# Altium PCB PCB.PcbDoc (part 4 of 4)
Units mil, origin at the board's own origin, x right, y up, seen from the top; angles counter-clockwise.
Board outline 6311.26 x 4737.49 mil, 2 copper layers (Top Layer, Bottom Layer); 252 components, 238 nets, 1140 pads, 635 vias.
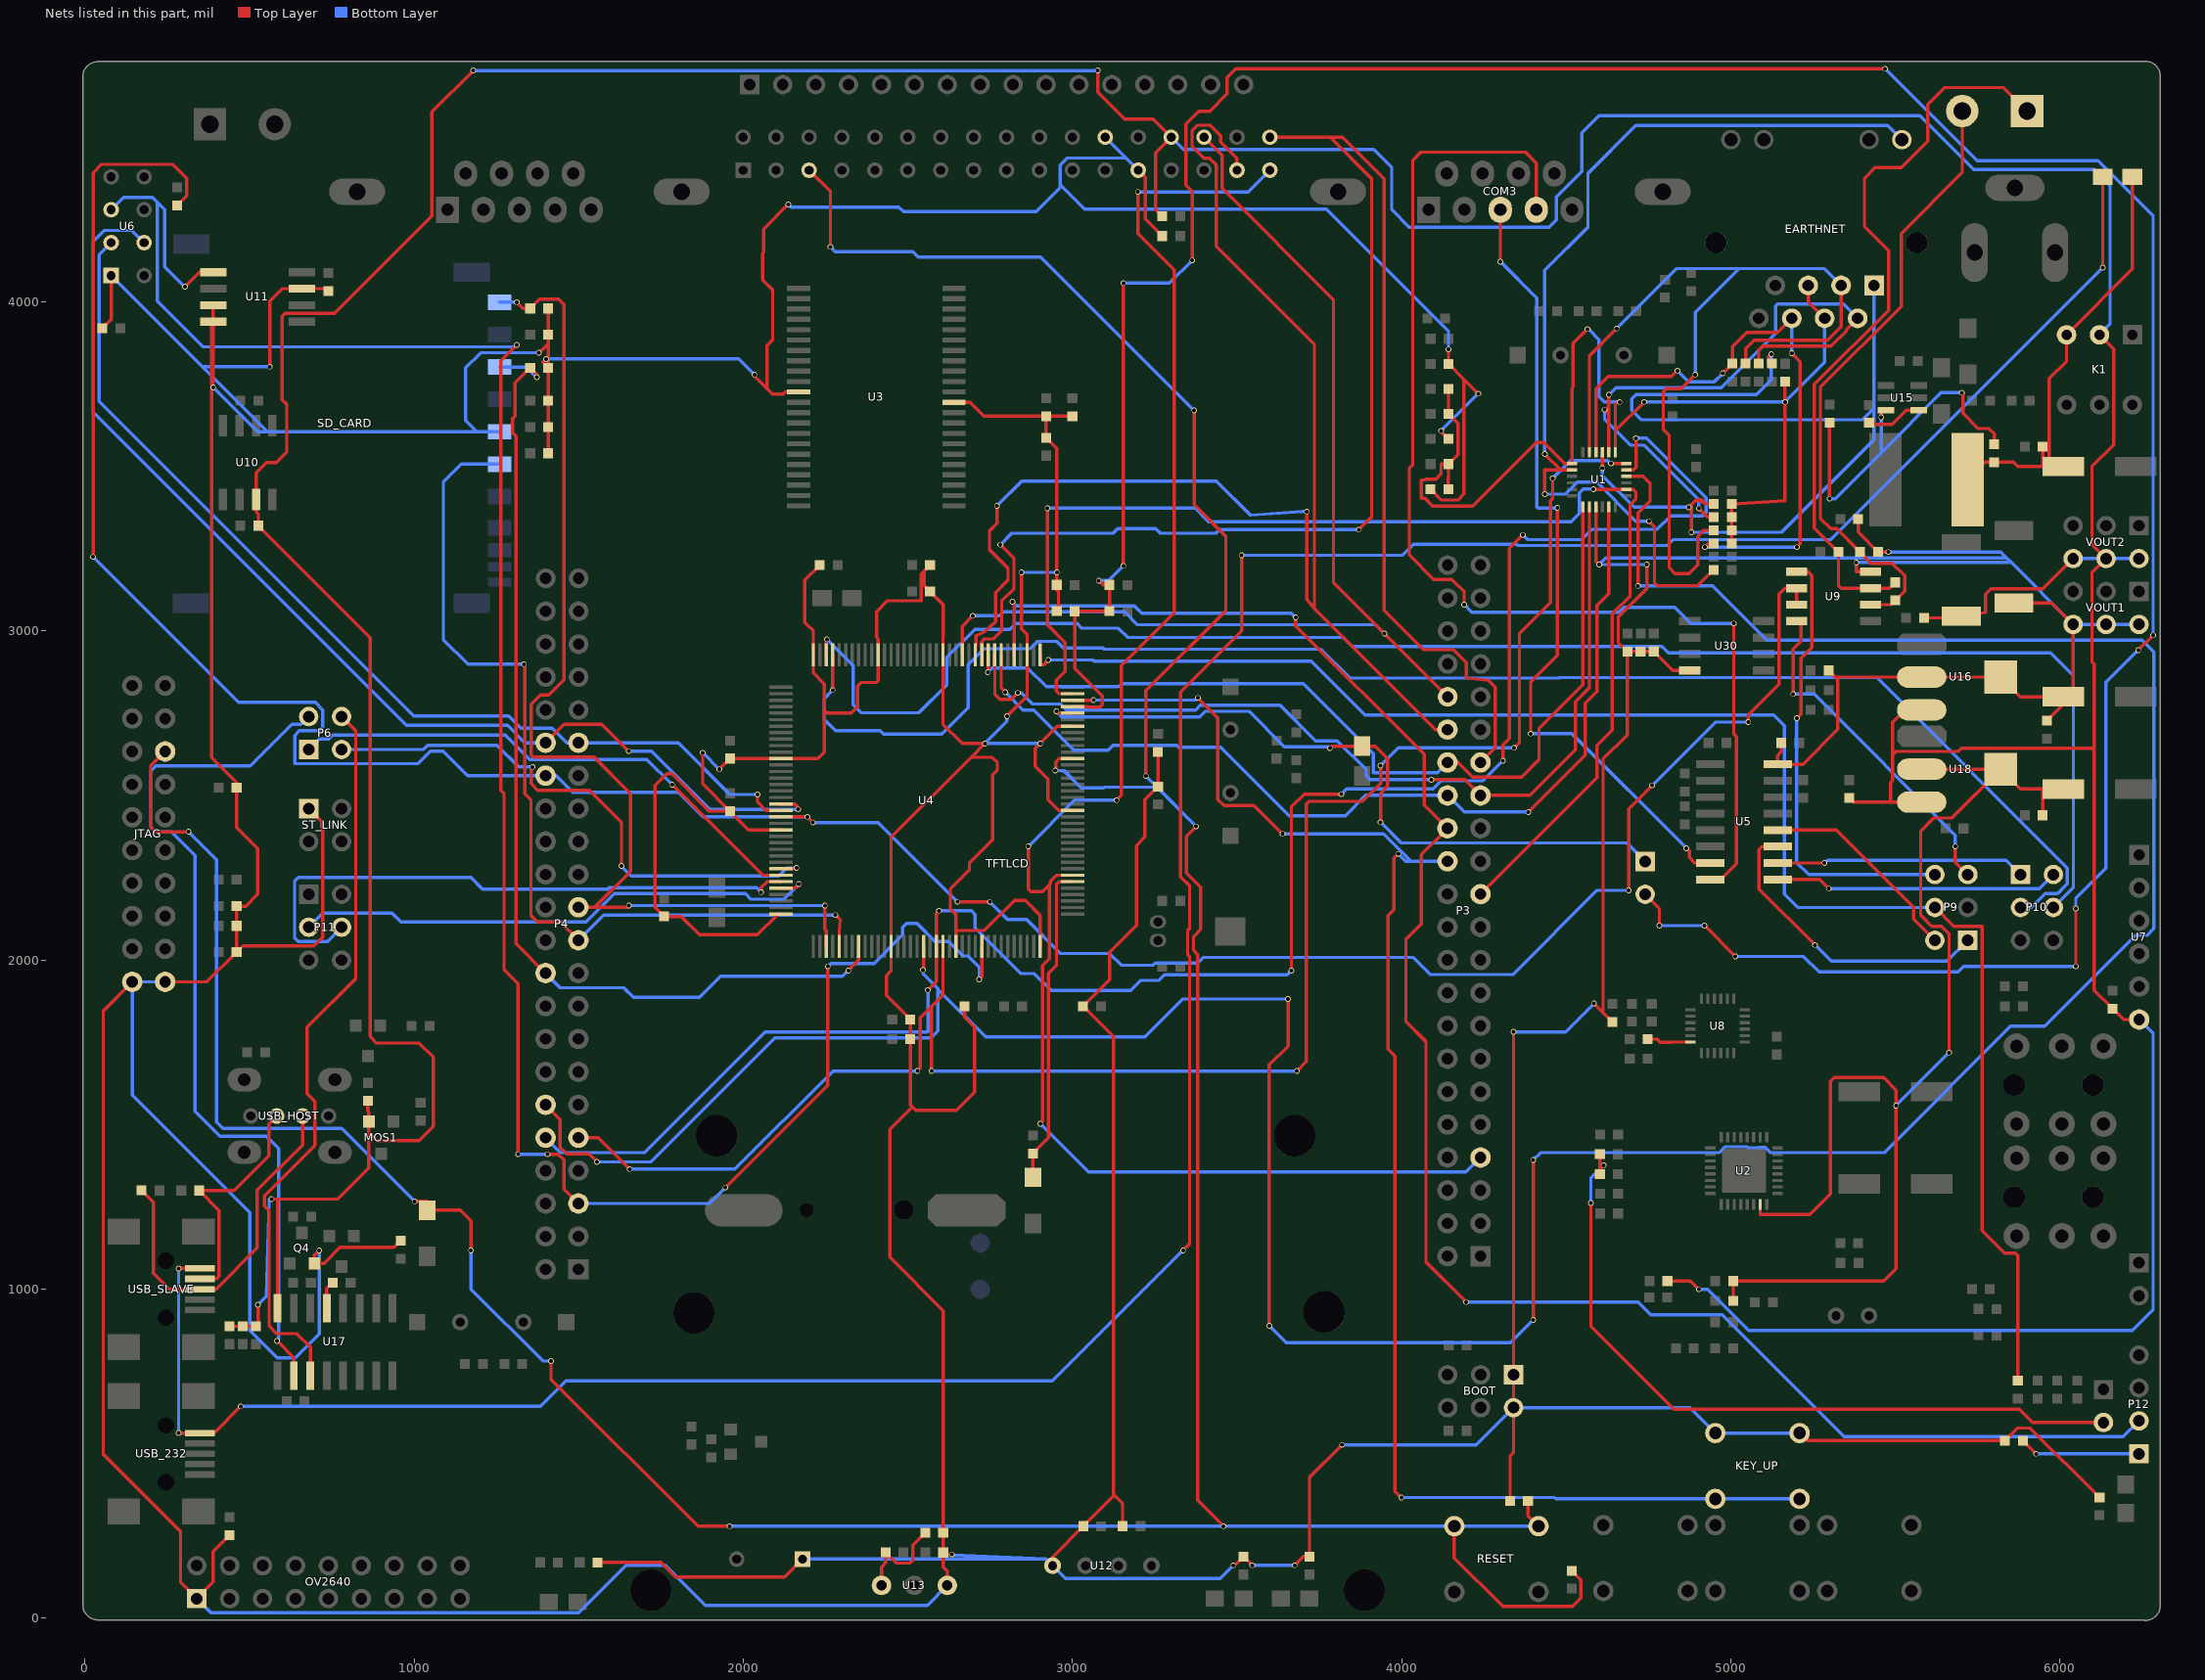
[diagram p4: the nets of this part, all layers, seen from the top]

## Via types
v1: diameter 17, hole 12, Top Layer to Bottom Layer, 622 vias
v2: diameter 25, hole 15, Top Layer to Bottom Layer, 9 vias
v3: diameter 275.59, hole 129.92, Top Layer to Bottom Layer, 4 vias

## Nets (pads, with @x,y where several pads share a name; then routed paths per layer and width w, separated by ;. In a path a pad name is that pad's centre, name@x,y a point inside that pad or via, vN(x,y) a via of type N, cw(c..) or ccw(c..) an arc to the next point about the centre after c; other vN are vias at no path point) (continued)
NetR38_2: 485.2 R38.2 R44.1 U9.6 | length 1911.7
  Top Layer w10: U9.6@5424.41,3080 5487,3080 R44.1@5500,3093 5528.06,3121.06 5528.06,3168 5490.06,3206 5426.56,3206 R38.2@5392.5,3240.06 5321.56,3311 5304,3311 5272,3343 5272,3740.01 5518,3986.01 5518,4208 5703.15,4393.15 485.2@5703.15,4580
NetR40_1: 485.1 R40.1 R44.2 U9.7 | length 2277.6
  Top Layer w10: R44.2@5500.06,3147.5 5482.56,3130 U9.7@5424.41,3130 5336,3130 5327,3139 R40.1@5327,3240 5254,3313 5254,3749.31 5479,3974.31 5479,4155 5406,4228 5406,4376 5438,4408 5518,4408 5598,4488 5598,4600 5649,4651 5829,4651 485.1@5900,4580
NetR45_2: R45.2 U8.12 | length 133.8
  Top Layer w9.84: 4819,1750.79 U8.12@4877.28,1750.79
  Top Layer w10: R45.2@4747.5,1759.94 4775.69,1759.94 4785.13,1750.5 4818.71,1750.5 4819,1750.79
NetR63_2: R63.2 R66.1 U13.1 | length 304.1
  Top Layer w10: U13.1@2420,100 2420,155.5 2432.5,168 R63.2@2432.5,200.06 2464.56,168 2507,168 2515,176 2515,222 R66.1@2553,260
NetR67_1: R67.1 R69.2 U15.3 | length 1356.4
  Top Layer w10: v1(5457,3649) 5457,3671.2 U15.3@5471,3671.2 ; v1(5702,3724) 5705,3721 5705,3662 5752,3615 5784,3615 5800.06,3598.94 R69.2@5800.06,3567.5 ; v1(5300,3402) R67.1@5300,3633 v1(5300,3402)
  Bottom Layer w10: v1(5300,3402) 5317,3402 5457,3542 ; v1(5457,3649) 5457,3542 ; v1(5702,3724) 5639,3724 5457,3542
NetR68_2: R68.2 U15.4 | length 171.2
  Top Layer w10: R68.2@5419.94,3632.5 5435.2,3632.5 5440.2,3627.5 5489.3,3627.5 5533,3671.2 U15.4@5571,3671.2
NetR71_1: R71.1 U17.13 | length 85.1
  Top Layer w10: U17.13@735,942.36 735,1002 R71.1@753,1020
NRF_CE: P4.34 U4.91 U6.3 | length 3454.7
  Top Layer w10: P4.34@1399.58,2660.43 1456.15,2717 1570,2717 v1(1652,2635) ; U4.91@2114.53,2474.62 2156.38,2474.62 2167,2464 v1(2167,2458)
  Bottom Layer w10: U6.3@180,4180 143,4217 58,4217 25,4184 25,3665 977,2713 1284,2713 1336.57,2660.43 P4.34@1399.58,2660.43 ; v1(1652,2635) 1721.5,2635 1898.5,2458 v1(2167,2458)
NRF_CS: P4.33 U4.92 U6.4 | length 3097.2
  Top Layer w10: v1(2043.52,2503) 2043.52,2480 2068.58,2454.94 U4.92@2114.53,2454.94
  Bottom Layer w10: U6.4@80,4180 43,4143 43,3698 999,2742 1287.43,2742 1325,2704.43 1420,2704.43 1464,2660.43 P4.33@1499.58,2660.43 1802.74,2660.43 1960.17,2503 v1(2043.52,2503)
NRF_IRQ: P4.32 R37.1 U4.93 U9.2 U9.3 | length 8512.1
  Top Layer w10: v1(25,3225) 25,4392 51,4418 267,4418 309,4376 309,4322 R37.1@280,4293 ; U4.93@2114.53,2435.25 v1(2194.75,2435.25) v1(2212,2418) ; v1(2651,2177) v1(2749,2177) ; v1(4690,2212) 4690,2460 v1(4761,2531) ; v1(5053,2723) 5053,2745 5146,2838 5146,3112 5164,3130 U9.2@5200,3130 U9.3@5200,3080
  Bottom Layer w10: v1(25,3225) 467,2783 700,2783 723,2760 723,2708 712,2697 651.94,2697 637.47,2682.53 637.47,2597 1012,2597 1049.5,2634.5 1088,2634.5 1162.07,2560.43 P4.32@1399.58,2560.43 1431.57,2560.43 1482,2510 1802.76,2510 1877.51,2435.25 v1(2194.75,2435.25) ; v1(2212,2418) 2410,2418 v1(2651,2177) ; v1(2749,2177) 2803,2123 2861,2123 2964,2020 3113,2020 3148.5,1984.5 3245.47,1984.5 3251.97,1991 3380,1991 3397,2008 4036,2008 4088,1956 4338.02,1956 4594.02,2212 v1(4690,2212) ; v1(4761,2531) 4953,2723 v1(5053,2723)
PA0: KEY_UP.2 P3.26 U4.34 | length 4849.1
  Top Layer w10: U4.34@3000.35,2789.58 3063.58,2789.58 v1(3064,2790) ; v1(3381,2797) 3442,2736 3442,2488 3460.13,2469.87 3552,2469.87 v1(3638.33,2383.55) ; v1(3990,2323) 3977.09,2310.09 3977.09,2153.81 3959.09,2135.81 3959.09,1729.53 3980,1708.63 3980,386 v1(3999,367)
  Bottom Layer w10: v1(3064,2790) 3374,2790 v1(3381,2797) ; v1(3638.33,2383.55) 3945.45,2383.55 3998,2331 4028.57,2300.43 ; v1(3990,2323) 4012.57,2300.43 4028.57,2300.43 ; v1(3999,367) 4464,367 4468,363 KEY_UP.2@4953,363 KEY_UP.2@5208.91,363 ; 4028.57,2300.43 P3.26@4139.58,2300.43 4028.57,2300.43
PA1: P3.23 U1.14 U4.35 | length 3944.6
  Top Layer w9.84: v1(4583,3430.47) U1.14@4682.72,3430.47 4704,3430.47 4711.58,3422.89 4711.58,3399.58 4694,3382
  Top Layer w10: v1(2924,3373) 2924,3019 2977.94,2965.06 2977.94,2876.88 2951,2849.94 2951,2818.27 2960,2809.27 U4.35@3000.35,2809.27 ; P3.23@4239.58,2200.43 4594,2554.85 4594,2652 4640,2698 4640,3052 4694,3106 4694,3382
  Bottom Layer w10: v1(2924,3373) 3373,3373 3413.72,3332.28 4514.55,3332.28 4540.08,3357.81 4540.08,3419.58 4552,3431.5 4581.97,3431.5 v1(4583,3430.47)
PA3: P9.4 R20.1 U4.37 | length 4978
  Top Layer w10: U4.37@2901.93,2927.38 2901.93,2897 2912,2897 v1(2927,2912) ; P9.4@5620,2160 5677,2103 5763,2103 5763,1178.52 5832,1109.52 5864.74,1109.52 5872,1102.26 R20.1@5872,722
  Bottom Layer w10: v1(2927,2912) 3062.25,2912 3065.75,2908.5 3725.05,2908.5 3888.55,2745 5130,2745 5163,2712 5163,2200 5203,2160 P9.4@5620,2160
PA5: P3.28 P12.2 U4.41 | length 5676.3
  Top Layer w10: v1(2818,3089) 2823.19,3083.81 U4.41@2823.19,2927.38 ; v1(3678,3041) 3678,3015.39 4068.26,2625.14 4068.26,2471.75 P3.28@4139.58,2400.43 4059.58,2320.43 4059.58,2110.29 4013.09,2063.81 4013.09,1813.41 4074,1752.5 4074,1083 v1(4196,961)
  Bottom Layer w10: v1(2818,3089) 2830.5,3076.5 3188.05,3076.5 3210.41,3054.14 3664.86,3054.14 v1(3678,3041) ; v1(4196,961) 4718.5,961 4757.5,922 4974,922 5344,552 6192,552 P12.2@6240,600
PA7: P3.30 U1.11 U4.43 | length 2949.7
  Top Layer w9.84: 4629.53,3113.24 U1.11@4629.53,3377.28
  Top Layer w10: U4.43@2783.82,2927.38 2783.82,2826.18 v1(2796,2814) ; v1(4385,2450) 4558,2623 4558,2780.5 4593.79,2816.29 4593.79,3077.5 4629.53,3113.24
  Bottom Layer w10: v1(2796,2814) 2850,2760 2883,2760 3005,2638 3108.5,2638 3123,2652.5 3317.5,2652.5 3323,2647 3451,2647 3659,2439 3829.57,2439 3891,2500.43 P3.30@4139.58,2500.43 4190,2450 v1(4385,2450)
PA9: P6.3 U4.101 | length 1724
  Top Layer w10: v1(1360,2587) 1355.58,2582.58 1355.58,2536 1375.58,2516 1533.51,2516 1630,2419.51 v1(1630,2286) ; U4.101@2114.53,2277.77 2159.77,2277.77 v1(2162,2280)
  Bottom Layer w10: P6.3@780,2640 1029,2640 1041.5,2652.5 1252.5,2652.5 1318,2587 v1(1360,2587) ; v1(1630,2286) 1659.86,2256.14 2108.48,2256.14 2132.34,2280 v1(2162,2280)
PA10: P6.1 U4.102 | length 1629.2
  Top Layer w10: v1(1784,2533) 2058.91,2258.09 U4.102@2114.53,2258.09
  Bottom Layer w10: P6.1@680,2640 712.18,2672.18 740.53,2672.18 752.35,2684 1277,2684 1351,2610 1707,2610 v1(1784,2533)
PA11: P11.4 U4.103 | length 1863
  Top Layer w10: v1(2054.4,2206.4) 2054.4,2220.8 2072,2238.4 U4.103@2114.53,2238.4
  Bottom Layer w10: P11.4@780,2100 737,2057 648,2057 637,2068 637,2240 648,2251 1173,2251 1208,2216 1588,2216 1592.14,2220.14 2040.66,2220.14 v1(2054.4,2206.4)
PA12: P11.3 U4.104 | length 1639.4
  Top Layer w10: U4.104@2114.53,2218.72 2156.72,2218.72 v1(2169,2231)
  Bottom Layer w10: P11.3@680,2100 723,2143 933,2143 960,2116 1523,2116 1609,2202 2006.9,2202 2024,2184.9 2122.9,2184.9 v1(2169,2231)
PB0: P3.31 TFTLCD.34 U4.46 | length 5389.3
  Top Layer w10: U4.46@2724.76,2927.38 2724.76,2968 2732.76,2976 2761,2976 2785,3000 2785,3090.5 2822.5,3128 2822.5,3220.5 v1(2781,3262) ; v1(3870,3308) 3909,3347 3909,4374 3782.76,4500.24 ; P3.31@4239.58,2600.43 4284,2644.85 4284,2830 4264,2850 4197,2857 4197,2904 4158,2943 4067,2943 3947,3063 3947,4374 3820.76,4500.24 3782.76,4500.24 ; 3782.76,4500.24 TFTLCD.34@3599.92,4500.24 3782.76,4500.24
  Bottom Layer w10: v1(2781,3262) 2816,3297 3123,3297 3137.5,3311.5 3252.5,3311.5 3267,3297 3436,3297 3447,3308 v1(3870,3308)
PB1: P3.34 TFTLCD.31 U4.47 | length 4255.8
  Top Layer w10: U4.47@2705.08,2927.38 2706.76,2963.68 2706.76,2985.35 2733.58,2998.58 2767,3028 2767,3117 2804.5,3154.5 2804.5,3190 2748,3246.5 2748,3304 2771,3327 v1(2771,3380.5) ; TFTLCD.31@3499.92,4400.24 3499.92,4436.08 3450,4486 3450,4505 3418.14,4536.86 3380.16,4536.86 3363.3,4520 3363.3,4473.54 3399.98,4436.86 3416,4436.86 3436.54,4416.31 3436.54,4169.48 3735,3871.02 3735,3068.57 ; v1(3712,3363) 3712,3096 3735,3068.57 ; P3.34@4139.58,2700.43 4103.15,2700.43 3735,3068.57
  Bottom Layer w10: v1(2771,3380.5) 2846.12,3455.62 3437.38,3455.62 3541,3352 3699,3363 v1(3712,3363)
PB5: P4.5 U4.135 U6.6 U11.5 | length 6818.7
  Top Layer w10: v1(304,4046) 348,4090 U11.5@390,4090 ; v1(1312,3869) 1263.5,3820.5 1263.5,2515.5 1273.5,2505.5 1273.5,1970.5 1316,1928 v1(1316,1410) ; v1(1406,1410) 1438,1410 1455,1393 1455,1305 P4.5@1499.58,1260.43 ; v1(1946,1309) 2257,1620 v1(2257,1981) ; v1(2717,1941) 2724.76,1948.76 U4.135@2724.76,2041.55
  Bottom Layer w10: U6.6@80,4280 117,4317 206,4317 ; v1(304,4046) 243,4107 243,4280 220,4303 ; v1(1312,3869) 1306.38,3863.38 358.71,3863.38 220,4002.08 220,4303 ; v1(1316,1410) v1(1406,1410) ; P4.5@1499.58,1260.43 1897.43,1260.43 v1(1946,1309) ; v1(2257,1981) 2266,1990 2397.46,1990 2484.5,2077.04 2484.5,2100 2496,2111.5 2528,2111.5 2582.5,2057 2624,2057 2668.43,2012.57 2682.81,2012.57 2717,1978.38 v1(2717,1941) ; 206,4317 220,4303 ; 206,4317 220,4303
PB10: P10.3 U4.69 | length 4702.7
  Top Layer w10: v1(2272.01,2820.34) U4.69@2272.01,2927.38
  Bottom Layer w10: v1(2272.01,2820.34) 2245.56,2793.89 2245.56,2731.94 2280,2697.5 2415.5,2697.5 2426.5,2686.5 2603.5,2686.5 2683.5,2766.5 2683.5,2897.76 2731.97,2946.23 2872,2946.23 2894.27,2968.5 2952,2968.5 2972.5,2948 3093.5,2948 3097,2944.5 3754.88,2944.5 3842.38,2857 4478.02,2857 4479.53,2858.51 5444.02,2858.51 6022.53,2280 6022.53,2232 5993.06,2202.53 5955.53,2202.53 5913,2160 P10.3@5880,2160
PB11: P10.4 U4.70 | length 4953.6
  Top Layer w10: U4.70@2252.32,2927.38 2252.32,2973.32 v1(2254,2975)
  Bottom Layer w10: v1(2254,2975) 2334,2895 2334,2776 2358.5,2751.5 2534,2751.5 2618.5,2836 2618.5,2920 2703.49,3004.99 2809.99,3004.99 2827.5,3022.5 3014.5,3022.5 3028.5,3008.5 3139.5,3008.5 3167.5,2980.5 3821.67,2980.5 3849.68,2952.5 4790.64,2952.5 4810.09,2933.05 5971.95,2933.05 6040.53,2864.47 6040.53,2220.53 P10.4@5980,2160
PC4: P3.29 U1.8 U4.44 | length 2863.4
  Top Layer w9.84: 4570.47,2827.47 U1.8@4570.47,3377.28
  Top Layer w10: U4.44@2764.13,2927.38 2764.13,2893.47 2764.5,2893.47 2764.5,2807.63 2780.13,2792 2814,2792 v1(2834,2812) ; v1(4090.5,2548) 4192,2548 P3.29@4239.58,2500.43 4389.43,2500.43 4528,2639 4528,2785 4570.47,2827.47
  Bottom Layer w10: v1(2834,2812) 2845,2812 2879,2778 2963.95,2778 2981.95,2760 3374,2760 3388,2774 3631,2774 3738.5,2666.5 3804.45,2666.5 3892.75,2578.2 3892.75,2559.25 3904,2548 v1(4090.5,2548)
PC5: P3.32 U1.7 U4.45 | length 2782.5
  Top Layer w9.84: 4550.79,2836.28 U1.7@4550.79,3377.28
  Top Layer w10: v1(2743,2875) 2744.45,2876.45 U4.45@2744.45,2927.38 ; P3.32@4139.58,2600.43 4172,2600.43 4216,2556.43 4364.93,2556.43 4417.27,2608.77 4417.27,2702.75 4550.79,2836.28
  Bottom Layer w10: v1(2743,2875) 2755.98,2887.98 2863.12,2887.98 2920.61,2830.49 3140.49,2830.49 3150,2840 3701.32,2840 3914.5,2626.82 3914.5,2569.5 4108.65,2569.5 P3.32@4139.58,2600.43
PC10: P4.23 R42.1 SD_CARD.9 U4.111 | length 3312.7
  Top Layer w10: v1(1312,3999.09) 1331.09,3980 R42.1@1353,3980 1381,4008 1439,4008 1455,3992 1455,2852 1409,2806 1384,2806 1355.58,2777.58 1355.58,2623.31 1362.46,2616.43 1546.94,2616.43 1657.46,2505.91 1657.46,2269.46 1548.43,2160.43 ; v1(1652.8,2165.8) 1647.43,2160.43 1548.43,2160.43 ; v1(2248,2165.8) 2248,2094.32 2252.32,2090 U4.111@2252.32,2041.55 ; 1548.43,2160.43 P4.23@1499.58,2160.43 1548.43,2160.43
  Bottom Layer w10: SD_CARD.9@1259.64,3999.09 v1(1312,3999.09) ; v1(1652.8,2165.8) v1(2248,2165.8)
PC12: P4.21 SD_CARD.5 U4.113 | length 2808.9
  Top Layer w10: v1(1334,2899) 1337,2896 1337,2505 1355,2487 1355,2136 1375,2116 1444,2116 P4.21@1499.58,2060.43 ; v1(2280,2137) 2294.85,2122.15 2291.69,2087.32 U4.113@2291.69,2041.55
  Bottom Layer w10: SD_CARD.5@1259.64,3506.97 1144,3506.97 1089,3451.97 1089,2974 1164,2899 v1(1334,2899) ; P4.21@1499.58,2060.43 1576.15,2137 v1(2280,2137)
PC13: P3.7 TFTLCD.33 U4.7 | length 5171.4
  Top Layer w10: v1(2866,2345.54) 2866,2216 2874,2208 2909,2208 2930.37,2229.37 ; v1(2902,1503) 2909.5,1510.5 2909.5,1984.05 2930.37,2004.93 2930.37,2229.37 ; U4.7@3000.35,2258.09 2952,2258.09 2933,2239.09 2933,2232 ; v1(3134,2486) 3149,2501 3149,2895.05 3309,3055.05 3309,4098 3199,4208 v1(3199,4334) ; 2930.37,2229.37 2933,2232 ; 2930.37,2229.37 2933,2232
  Bottom Layer w10: v1(2866,2345.54) 3006.46,2486 v1(3134,2486) ; v1(2902,1503) 3049,1356 4195.15,1356 P3.7@4239.58,1400.43 ; v1(3199,4334) 3533.69,4334 TFTLCD.33@3599.92,4400.24
PD2: P4.20 R39.1 SD_CARD.2 U4.116 | length 3136.6
  Top Layer w10: v1(1373,3771) 1373,3780 R39.1@1353,3800 1307,3754 1307,3653 1299.5,3645.5 1299.5,3602.31 1309.5,3592.31 1309.5,2050.5 P4.20@1399.58,1960.43 ; v1(2319.24,1968.31) 2350.75,1999.82 U4.116@2350.75,2041.55
  Bottom Layer w10: SD_CARD.2@1260,3802 1342,3802 v1(1373,3771) ; P4.20@1399.58,1960.43 1444,1916 1637,1916 1666.25,1886.75 1867.74,1886.75 1931.49,1950.5 2301.43,1950.5 v1(2319.24,1968.31)
PF11: P3.36 TFTLCD.30 U4.49 | length 3693.5
  Top Layer w10: U4.49@2665.71,2927.38 2665.71,3014.51 v1(2697.38,3046.18) ; TFTLCD.30@3399.92,4500.24 3454.54,4445.61 3454.54,4345.61 3793,4007.16 3793,3147 v1(3948,2992) ; v1(3948,2992) P3.36@4140,2800 v1(3948,2992)
  Bottom Layer w10: v1(2697.38,3046.18) 2779.18,3046.18 2791.5,3058.5 3158.48,3058.5 3198.12,3018.86 3921.14,3018.86 v1(3948,2992)
PG11: P4.12 U1.16 U4.126 | length 10346.9
  Top Layer w9.84: U1.16@4682.72,3469.84 4733.16,3469.84
  Top Layer w10: P4.12@1399.58,1560.43 1444,1516 1444,1431 1464,1411 1532,1411 v1(1556,1387) ; v1@2547.6,1971.6 U4.126@2547.6,2041.55 ; v1(3598,889) 3598,1682 3655,1739 v1(3655,1882) ; v1(4400,907) v1(4400,1393) ; v1(4718,3137) 4718,3359 4755,3396 4755,3448 4733.16,3469.84
  Bottom Layer w10: v1(1556,1387) 1720,1387 2096.5,1763.5 2570.28,1763.5 2590.78,1784 2590.78,1909.22 ; 2546,1959 2590.78,1914.22 ; 2591.5,1911.5 2736.5,1766.5 3220,1766.5 3335.5,1882 v1(3655,1882) ; v1(3598,889) 3649.93,837.07 4330.07,837.07 v1(4400,907) ; v1(4400,1393) 4422,1415 4964.45,1415 4982.19,1432.74 5050.56,1432.74 ; v1(4718,3137) 4944.48,3137 5109.48,2972 6249,2972 6285,2936 6285,2096 6264,2075 6228.96,2075 5952.96,1799 5850,1799 5466,1415 5121.06,1415 5105.56,1430.5 5084.44,1430.5 ; 5053.31,1430 5083.94,1430
  other v1: 2546,1970
PG13: P4.10 U1.17 U4.128 | length 5894
  Top Layer w9.84: U1.17@4682.72,3489.53 4704,3489.53 4712,3497.53 v1(4712,3586)
  Top Layer w10: v1(2561,1909) 2586.97,1934.97 U4.128@2586.97,2041.55 2586.97,2141.97 v1(2595,2150) ; v1(3665,1968) 3665,2465 3704,2504 v1(3817,2504) ; v1(4308,2606) 4308,2654 4327,2673 4327,3251 v1(4368,3292)
  Bottom Layer w10: P4.10@1399.58,1460.43 1445,1415 1700,1415 2066.5,1781.5 2560,1781.5 2561,1782.5 v1(2561,1909) ; v1(2595,2150) 2693.54,2150 2704.69,2138.85 2704.69,2097.52 2843.21,1959 2884,1959 2935.5,1907.5 3177.5,1907.5 3208.5,1938.5 3263.5,1938.5 3280,1955 3652,1955 v1(3665,1968) ; v1(3817,2504) 3833,2520 4096,2520 4121,2545 4247,2545 v1(4308,2606) ; v1(4368,3292) 4382.25,3277.75 4547.75,3277.75 4579,3309 4777,3309 4818,3350 4915,3350 4925,3360 4925,3405 4744,3586 v1(4712,3586)
PG14: P4.9 U1.18 U4.129 | length 5779.9
  Top Layer w9.84: v1@4636,3509.21 U1.18@4682.72,3509.21
  Top Layer w10: P4.9@1499.58,1460.43 1559.57,1460.43 v1(1655,1365) ; v1(2529,1663) 2538,1672 2538,1825 2606.65,1893.65 ; v1(2572,1663) 2572,1858.91 2606.65,1893.57 2606.65,1893.65 ; v1(3682,1663) 3711,1692 3711,2474 3719.5,2482.5 3881.5,2482.5 3936,2537 v1(3936,2591) ; v1(4342,2645) 4358,2661 4358,2993 4451.95,3086.95 4451.95,3395.5 4459,3402.55 v1(4459,3464) ; v1(4635.79,3509) v1@4636,3509.21 ; 2606.65,1893.65 U4.129@2606.65,2041.55 2606.65,1893.65
  Bottom Layer w10: v1(1655,1365) 1975,1365 2273,1663 v1(2529,1663) ; v1(2572,1663) v1(3682,1663) ; v1(3936,2591) 3990,2645 v1(4342,2645) ; v1(4459,3464) 4513,3518 4626.79,3518 v1(4635.79,3509)
PWM_AUDIO: C20.2 C21.2 P2.2 | length 2275.8
  Top Layer w10: v1(4575,1262) 4575,887 4827,635 5876,635 5916,595 P2.2@6132,595 ; C20.2@4602.5,1410.06 4602.5,1377 4602.5,1365.5 ; v1(4614,1377) 4602.5,1365.5 ; 4602.5,1365.5 C21.2@4602.5,1350.06 4602.5,1365.5
  Bottom Layer w10: v1(4575,1262) 4575,1338 v1(4614,1377)
RESET: C48.2 D7.1 JTAG.15 R24.1 RESET.1 TFTLCD.5 U4.25 | length 13240.7
  Top Layer w10: JTAG.15@244,2634 200,2590 200,2406 216,2390 v1(315,2390) ; v1(1002,1267) 1040,1267 D7.1@1040,1240 1141,1240 1173,1208 v1(1173,1118) ; v1(1416,782) 1416,726.2 1862.2,280 v1(1959,280) ; TFTLCD.5@2200,4400 2265,4335 v1(2265,4167) ; v1(2948,2576) 2949,2577 2949,2601.42 2960,2612.42 U4.25@3000.35,2612.42 ; v1(3223,2559) 3223,2819 3466,3062 3466,3288 3370,3384 v1(3370,3670) ; v1(3376,2406) 3346.5,2376.5 3346.5,2264 3389,2221.5 3389,2093 3368.05,2072.05 3368.05,2029.05 3380.12,2016.98 3380.12,358.88 v1(3459,280) ; RESET.1@4160,280 4160,184 4308,36 4519,36 4545,62 4545,116.56 C48.2@4517.06,144.5 ; R24.1@4384,357 4384,311.91 RESET.1@4415.91,280
  Bottom Layer w10: v1(315,2390) 400.5,2304.5 400.5,1508.5 420,1489 780,1489 v1(1002,1267) ; v1(1173,1118) 1173,1000 1391,782 v1(1416,782) ; v1(1959,280) v1(3459,280) ; v1(2265,4167) 2279,4153 2515.18,4153 2532.18,4136 2904,4136 v1(3370,3670) ; v1(2948,2576) 2974,2576 3027,2523 3095.5,2523 3098,2525.5 3256.5,2525.5 ; v1(3223,2559) 3256.5,2525.5 ; RESET.1@4415.91,280 RESET.1@4160,280 ; 3256.5,2525.5 v1(3376,2406) 3256.5,2525.5 ; v1(3459,280) RESET.1@4160,280 ; v1(3459,280) RESET.1@4160,280
RS485_RX: P9.5 U9.4 | length 1049.7
  Top Layer w10: v1(5189.5,2808.5) 5189.5,2946 5213,2969.5 5213,3030 U9.4@5200,3030 ; v1(5682,2345) 5682,2298 P9.5@5720,2260
  Bottom Layer w10: v1(5189.5,2808.5) 5253,2808.5 5682,2379.5 v1(5682,2345)
RS485_TX: P9.6 U9.1 | length 1376.2
  Top Layer w10: U9.1@5200,3180 5234,3180 5246,3168 5246,2950 5213,2917 5213,2747.51 v1(5200.49,2735)
  Bottom Layer w10: v1(5200.49,2735) 5200.49,2296 5236.49,2260 P9.6@5620,2260
RXD: P6.4 U17.3 | length 2248.5
  Top Layer w10: U17.3@685,737.64 685,824 644,865 583,865 560,888 560,1237.71 545.5,1252.21 545.5,1283.81 699,1437.31 699,1570 675,1594 675,1796 823,1944 823,2697 P6.4@780,2740
SPEED_LED: EARTHNET.9 R9.1 U1.2 | length 2975.2
  Top Layer w9.84: 4435.47,3489.53 4483,3489.53 ; 4483,3489.53 U1.2@4517.28,3489.53 4483,3489.53
  Top Layer w10: v1(4435,3416) 4435,3489.06 4435.47,3489.53 ; v1(4435,3537.53) 4483,3489.53 ; v1(4751.5,3333.5) 4768,3317 4768,3146 4776,3138 4900,3138 R9.1@4948,3186
  Bottom Layer w10: v1(4435,3416) 4498.03,3416 4534,3451.97 4593.03,3451.97 4711.5,3333.5 v1(4751.5,3333.5) ; v1(4435,3537.53) 4435,4096 4566,4227 4566,4391 4711,4536 5476.76,4536 EARTHNET.9@5519.84,4492.91
TPAD: P12.1 R64.1 | length 369.6
  Top Layer w10: R64.1@5887,540 v1(5927,500)
  Bottom Layer w10: v1(5927,500) P12.1@6240,500
TPRX+: C32.2 EARTHNET.3 R5.1 U1.23 | length 3222.9
  Top Layer w9.84: U1.23@4570.47,3542.72 4570.47,3836.47
  Top Layer w10: 4570.47,3836.47 v1(4653,3919) ; v1(4892,3779) 4849,3736 4803,3736 4795,3728 4795,3611 4812.97,3593.03 4812.97,3192 4830.47,3174.5 4872.5,3174.5 4899.5,3201.5 4899.5,3288 4917.5,3306 R5.1@4948,3306 ; C32.2@5045,3812.5 5045,3858 5070.5,3883.5 5293.7,3883.5 5335.2,3925 EARTHNET.3@5335.2,4050
  Bottom Layer w10: v1(4653,3919) 4835,4101 5025,4101 ; v1(4892,3779) 4892,3968 5025,4101 ; EARTHNET.3@5335.2,4050 5284.2,4101 ; 5025,4101 5284.2,4101 ; 5025,4101 5284.2,4101
TPRX-: C33.2 EARTHNET.6 R6.1 U1.22 | length 1956.6
  Top Layer w9.84: U1.22@4590.16,3542.72 4590.16,3736
  Top Layer w10: 4590.16,3736 4627.16,3773 4820,3773 v1(4838,3791) ; v1(4921,3255) 4932,3266 R6.1@4948,3266 ; v1(4975.5,3783) C33.2@5005,3812.5 5005,3864 5048,3907 5142.2,3907 EARTHNET.6@5185.2,3950 ; v1(5185.2,3844) 5210.87,3818.32 5210.87,3264.87 v1(5201,3255)
  Bottom Layer w10: v1(4838,3791) 4872,3757 4949.5,3757 v1(4975.5,3783) ; v1(4921,3255) v1(5201,3255) ; v1(5185.2,3844) EARTHNET.6@5185.2,3950
TPTX+: C30.2 EARTHNET.1 R3.1 U1.21 | length 3109.7
  Top Layer w9.84: v1(4609.84,3494.98) U1.21@4609.84,3542.72
  Top Layer w10: v1(4872.5,3376) 4880,3383.5 ; v1(4880,3299.95) 4880,3376 4880,3383.5 ; R3.1@4948,3386 4924.5,3386 ; v1(5123,3841) 5113,3831 5113,3812.5 C30.2@5125,3812.5 ; 4880,3383.5 4896,3399.5 ; 4880,3383.5 4896,3399.5 ; 4896,3399.5 4924.5,3386 ; 4896,3399.5 4911,3399.5 4924.5,3386
  Bottom Layer w10: v1(4609.84,3494.98) 4609.84,3472.12 4705.96,3376 v1(4872.5,3376) ; v1(4880,3299.95) 5154.26,3299.95 5435.2,3580.89 5435.2,3677.2 ; v1(5123,3841) 5123,3763 5078,3718 4712,3718 4699,3705 4699,3671 4728,3642 5400,3642 5435.2,3677.2 ; EARTHNET.1@5435.2,4050 5435.2,3677.2
TPTX-: C31.2 EARTHNET.2 R4.1 U1.20 | length 2129.4
  Top Layer w9.84: v1(4629.53,3717.53) 4629.53,3672.48 4629.53,3659.43 ; 4629.53,3659.43 U1.20@4629.53,3542.72 4629.53,3659.43
  Top Layer w10: v1(4616.48,3672.48) 4629.53,3659.43 ; v1(4903,3372.26) 4929.26,3346 R4.1@4948,3346 ; C31.2@5085,3812.5 5085,3855.14 5095.36,3865.5 5304.58,3865.5 5351.08,3912 5351.08,3915.89 EARTHNET.2@5385.2,3950
  Bottom Layer w10: v1(4616.48,3672.48) 4616.48,3644.02 4696,3564.5 4737.07,3564.5 4903,3398.57 v1(4903,3372.26) ; v1(4629.53,3717.53) 4651,3739 4971,3739 5136,3904 5136,3987 5142,3993 5342.2,3993 EARTHNET.2@5385.2,3950
TXD: P6.2 U17.2 | length 2679.4
  Top Layer w10: v1(584,843) 635,792 U17.2@635,737.64
  Bottom Layer w10: v1(584,843) 588.75,847.75 588.75,1427.25 551,1465 411,1465 335,1541 335,2318 264,2389 216,2389 200,2405 200,2574 216,2590 503,2590 629,2716 656,2716 P6.2@680,2740
U2_RX: P9.1 U5.11 | length 930.9
  Top Layer w10: U5.11@5142.36,2345 5095,2345 5086,2336 5086,2216 v1(5256,2046)
  Bottom Layer w10: v1(5256,2046) 5305,1997 5657,1997 P9.1@5720,2060
U2_TX: P9.2 U5.12 | length 637.5
  Top Layer w10: U5.12@5142.36,2395 5320.96,2395 5555.43,2160.53 5555.43,2124.57 P9.2@5620,2060
U3_232RX: COM3.4 U5.8 | length 3684.7
  Top Layer w10: v1(4190,3080) 4190,3119 4152,3157 4097,3157 4023.5,3230.5 4023.5,3495.06 4034,3505.56 4034,4431 4058,4455 4376,4455 4409,4422 COM3.4@4409,4280 ; U5.8@4937.64,2245 4969,2245 5017,2293 5017,2680 5009,2688 v1(5009,3023)
  Bottom Layer w10: v1(4190,3080) 4213,3057 4661,3057 4676,3072 4830,3072 4879,3023 v1(5009,3023)
U3_232TX: COM3.3 U5.7 | length 2452
  Top Layer w10: v1(4300,4122) COM3.3@4300,4280 ; v1(4392,2688) 4392,2844 4473.45,2925.45 v1(4473.45,3374) ; v1(4865,2340) 4874,2331 4874,2312 4891,2295 U5.7@4937.64,2295
  Bottom Layer w10: v1(4300,4122) 4411,4011 4411,3377 4414,3374 v1(4473.45,3374) ; v1(4392,2688) 4517,2688 v1(4865,2340)
U3_RX: P10.1 U5.10 | length 759.1
  Top Layer w10: U5.10@5142.36,2295 v1(5284.63,2295)
  Bottom Layer w10: v1(5284.63,2295) 5293.02,2303.39 5836.61,2303.39 P10.1@5880,2260
U3_TX: P10.2 U5.9 | length 867
  Top Layer w10: U5.9@5142.36,2245 5269.71,2245 v1(5297.71,2217)
  Bottom Layer w10: v1(5297.71,2217) 5937,2217 P10.2@5980,2260
USB_DM: R52.2 USB_HOST.2 USB_SLAVE.2 | length 733.1
  Top Layer w10: USB_SLAVE.2@349.06,1031.5 399.5,1031.5 408,1040 408,1239.44 R52.2@347.5,1299.94 452.94,1299.94 559,1406 559,1502.47 USB_HOST.2@582.83,1526.3
USB_DP: R53.2 USB_HOST.3 USB_SLAVE.3 | length 1111.1
  Top Layer w10: R53.2@172.5,1300.06 208.69,1263.87 208.69,1049 257.69,1000 USB_SLAVE.3@349.06,1000 398,1000 524,1126 524,1301 661.57,1438.57 USB_HOST.3@661.57,1526.3
VBAT: C61.2 D2.2 U4.6 | length 971.9
  Top Layer w10: D2.2@2880,1340 2880,1376 2879.94,1376.06 C61.2@2879.94,1412.5 2927.5,1460.06 2927.5,1959.65 2951.5,1983.65 2951.5,2229.9 2960,2238.4 U4.6@3000.35,2238.4
VBTN: C84.2 C85.1 F1.1 K1.3 L2.1 R69.1 | length 1405.1
  Top Layer w10: L2.1@5720,3460 5773,3513 R69.1@5800,3513 5859,3513 5872,3500 C85.1@5947.5,3500 ; C84.2@5947.5,3559.94 C85.1@5947.5,3500 ; F1.1@6220,4380.06 6220,4100 K1.3@6020,3900 6020,3820 5967,3767 5967,3559.94 C85.1@5967,3500 ; C85.1@5947.5,3500 C85.1@5967,3500 ; C85.1@5967,3500 C85.1@6010,3500 C85.1@5967,3500
VCC3.3: BEEP.1 BOOT.1 BOOT.2 C13.2 C27.2 C36.2 C37.2 C39.1 C49.2 C50.2 C51.2 C52.2 C53.2 C54.2 C55.2 C56.2 C57.2 C58.2 C59.2 C60.2 C63.1 C65.1 C70.1 C71.1 C72.2 C78.1 C79.2 C81.1 C82.2 C86.2 C88.1 D6.2 JTAG.1 JTAG.2 KEY_UP.1 L1.2 OV2640.1 Q4.1 R7.1 R22.1 R24.2 R25.2 R27.2 R28.1 R29.1 R30.1 R33.1 R38.1 R39.2 R41.2 R42.2 R43.2 R46.2 R47.2 R48.2 R49.2 R50.2 R55.1 R58.2 R62.2 R64.2 R65.2 R66.2 R70.2 SD_CARD.4 ST_LINK.1 TFTLCD.24 TFTLCD.25 U1.9 U3.11 U3.33 U4.17 U4.30 U4.39 U4.52 U4.62 U4.72 U4.84 U4.95 U4.108 U4.121 U4.131 U4.144 U5.16 U6.2 U9.8 U11.3 U11.7 U11.8 U12.1 U13.3 U16.2 U16.4 U30.8 VOUT1.2 VOUT1.4 VOUT1.6 | length 47701.2
  Top Layer w9.84: U1.9@4590.16,3377.28 4590.16,3211.84 v1(4600,3202)
  Top Layer w10: C70.1@53,3920 80,3947 U6.2@80,4080 ; JTAG.2@144,1934 56,1846 56,498 291,263 291,109 OV2640.1@340,60 390,110 390,203 C65.1@440,253 ; JTAG.1@244,1934 371,1934 R28.1@461,2024 ; v1(390,3740) U11.8@390,3940 ; U11.7@390,3990 U11.8@390,3940 ; v1(562,3803) 562,4002.06 600,4040.06 U11.3@660,4040.06 732.94,4040.06 C78.1@740,4033 ; ST_LINK.1@680,2460 719.47,2420.53 719.47,2403 723,2399.47 723,2070 696,2043 480,2043 R28.1@461,2024 ; v1(712,1118) 697.4,1103.4 Q4.1@697.4,1078.74 727,1078.74 775.26,1127 939.56,1127 R70.2@960.06,1147.5 ; v1(1379.38,3845.38) 1407.5,3873.5 ; v1(1401.56,3826.44) 1391.28,3816.15 R39.2@1407.5,3799.94 ; C72.2@1407.5,3539.94 R43.2@1407.5,3619.94 R50.2@1407.5,3699.94 R39.2@1407.5,3799.94 ; R42.2@1407.5,3979.94 R48.2@1407.5,3899.94 ; R58.2@1557.5,169.94 1750.06,169.94 1794.62,125.38 2125.38,125.38 BEEP.1@2180,180 ; v1(1877,2630) 1877,2535.44 C56.2@1959.94,2452.5 ; v1(1927.22,2579.78) C55.2@1959.94,2612.5 1976.9,2612.5 1976.98,2612.42 U4.84@2114.53,2612.42 2226.42,2612.42 2246,2632 2246,2759.56 ; v1(2034,3779) 2034,3774.5 2072,3736.5 ; U4.108@2114.53,2139.98 2106.01,2139.98 2043.03,2077 1867,2077 1811.5,2132.5 C57.2@1759.94,2132.5 1732,2160.44 1732,2531 1767,2566 1784,2566 1897.5,2452.5 C56.2@1959.94,2452.5 ; U4.95@2114.53,2395.88 2016.55,2395.88 C56.2@1959.94,2452.5 ; v1(2137,4296) 2062,4221 2062,4151 2058.5,4147.5 2058.5,4066.83 2089.5,4035.83 2089.5,3884.5 2072,3867 2072,3736.5 ; U3.33@2167.91,3726.43 2127.43,3726.43 2121,3720 2088.5,3720 ; C54.2@2232.5,3200.06 2187,3154.56 2187,3025.95 2212.95,3000 U4.72@2212.95,2927.38 2212.95,2890 2212.95,2872.05 2246,2839 2246,2759.56 ; 2245.56,2760 2246,2759.56 ; U13.3@2620,100 2620,143 2607.5,155.5 C82.2@2607.5,194 ; v1(2634,194) C82.2@2607.5,194 ; U3.11@2640.35,3694.94 2689,3694.94 2731.44,3652.5 C36.2@2919.94,3652.5 ; R27.2@2672.5,1860.06 2672.5,1825.92 2702.5,1795.92 2702.5,1598 2648,1543.5 2524,1543.5 2513.75,1553.75 ; v1(2801,2741) 2862.56,2802.56 U4.39@2862.56,2927.38 2862.56,2989 2845,3006.56 v1(2845,3178) ; U4.144@2901.93,2041.55 2901.93,2136 2856.93,2181 2824,2181 2733,2090 2646.02,2090 ; v1(2902,2658) v1@2901.67,2658.33 ; U12.1@2940,160 2940,187 R55.1@3033,280 3124.86,371.86 3124.86,376.14 ; R25.2@2952.5,3060.06 2957.73,3065.3 2957.73,3123.8 2952.5,3123.8 C52.2@2952.5,3140.06 ; C37.2@2999.94,3652.5 C36.2@2919.94,3652.5 ; U4.17@3000.35,2454.94 2958.58,2454.94 2925.52,2488 2925.52,2549.48 2886.5,2588.5 2886.5,2643.16 v1@2901.67,2658.33 ; U4.30@3000.35,2710.84 2954.18,2710.84 ; C79.2@3152.5,280.06 3152.5,348.5 3124.86,376.14 ; TFTLCD.25@3199.92,4400.24 3221.5,4378.66 3221.5,4251.5 C39.1@3273,4200 ; C49.2@3259.94,2632.5 3259.94,2579.13 3260.06,2579 C50.2@3260.06,2527.5 3220.5,2487.94 3220.5,2373.97 3194.53,2348 3194.53,2106.03 3112.5,2024 3112.5,1940.06 C60.2@3032.5,1860.06 3124.86,1767.7 3124.86,376.14 ; v1(3489,161) 3493.56,161 R46.2@3520.06,187.5 v1(3546.56,161) ; v1(3675,161) 3701.5,187.5 R41.2@3720.06,187.5 3720.06,428.06 v1(3819,527) ; L1.2@4087.5,3431.06 4120.56,3398 4171,3398 4189,3416 4189,3765.19 ; v1(4120,3608.19) 4120,3605.81 C27.2@4142.5,3583.31 ; v1(4142.5,3855.5) C13.2@4142.5,3811.69 ; v1(4233,3721.19) 4189,3765.19 ; R24.2@4329.5,357.06 4329.5,493 4340,503.5 BOOT.2@4340,640 BOOT.1@4340,740 v1(4340,1782) ; v1(4584.22,1868.22) 4612,1840.44 ; v1(4745,3202) 4745,3129 4658,3042 4658,2965.44 R62.2@4685.94,2937.5 ; U30.8@4875.59,2880 4824,2880 C81.1@4766,2938 4745.5,2938 4745,2937.5 R65.2@4725.94,2937.5 R62.2@4685.94,2937.5 ; C63.1@5153,2660 5153,2632.64 5142.36,2622 U5.16@5142.36,2595 5219,2595 5325,2701 5325,2852 5317.03,2859.97 ; KEY_UP.1@5208.91,563 5231.84,540.06 R64.2@5832.5,540.06 5870.44,578 5909.56,578 R47.2@6120.06,367.5 ; v1(5381,3208) 5381,3180 U9.8@5424.41,3180 ; C71.1@5387,3340 5387,3300 R38.1@5447,3240 v1(5479,3240) ; D6.2@5860,3085 5975,3085 VOUT1.6@6040,3020 6040,2830 C88.1@6010,2800 ; C86.2@5960.06,2727.5 6010,2777.44 C88.1@6010,2800 ; U11.8@390,3940 385,3940 385,3740 385,2616 461,2540 R33.1@461,2524 461,2403 525,2339 525,2200 489,2164 R30.1@461,2164 R29.1@461,2104 461,2100.94 461.5,2100.94 461.5,2064.5 461,2064 R28.1@461,2024 ; R39.2@1407.5,3799.94 1407.5,3826.44 1407.5,3873.5 ; 1407.5,3873.5 R48.2@1407.5,3899.94 ; 1407.5,3873.5 R48.2@1407.5,3899.94 ; 2072,3736.5 2088.5,3720 ; 2072,3736.5 2088.5,3720 ; 2246,2759.56 2254.67,2750.89 2328,2750.89 2347,2769.89 2347,2832 2358.65,2843.65 2404.8,2843.65 2409.67,2848.53 2409.67,2901.5 2409.8,2901.5 U4.62@2409.8,2927.38 2409.8,2976 2405,2980.8 2405,3059 2438,3092 2541,3092 2541,3173.44 2549.5,3181.94 ; 2449.17,2373.17 2692,2616 ; 2449.17,2373.17 U4.121@2449.17,2041.55 2449.17,1966.63 2435.04,1952.5 2435.04,1892.39 C59.2@2507.5,1819.94 C58.2@2507.5,1759.94 2507.5,1560 ; 2449.17,2373.17 2692,2616 ; 2507.5,1560 2513.75,1553.75 ; 2507.5,1560 2513.75,1553.75 ; 2513.75,1553.75 2445,1485 2445,1097 2607.5,934.5 R66.2@2607.5,259.94 C82.2@2607.5,199.94 ; 2549.5,3181.94 2549.5,3137.93 C53.2@2567.5,3119.94 2607.5,3079.94 2607.5,2986.5 2606.65,2985.65 U4.52@2606.65,2927.38 2606.65,2717 2665.65,2658 v1(2734,2658) 2692,2616 ; 2549.5,3181.94 C51.2@2567.5,3199.94 2549.5,3181.94 ; C82.2@2607.5,194 C82.2@2607.5,199.94 ; C82.2@2607.5,194 C82.2@2607.5,199.94 ; 2646.02,2090 2646.02,2138.98 2629,2156 2629,2215 2687,2273 2687,2294 2758,2365 2758,2564 2772,2578 2772,2600 2756,2616 2692,2616 ; 2646.02,2090 U4.131@2646.02,2041.55 2646.02,2090 ; v1@2901.67,2658.33 2954.18,2710.84 ; v1@2901.67,2658.33 2954.18,2710.84 ; C36.2@2919.94,3652.5 2919.94,3619.06 2920,3619 R22.1@2920,3587 2952.5,3554.5 v1(2952.5,3178) ; C52.2@2952.5,3140.06 v1(2952.5,3178) ; C52.2@2952.5,3140.06 v1(2952.5,3178) ; C13.2@4142.5,3811.69 4189,3765.19 ; C13.2@4142.5,3811.69 4189,3765.19 ; 4612,1840.44 4612,2610.55 4685.94,2684.49 R62.2@4685.94,2937.5 ; 4612,1840.44 R49.2@4639.94,1812.5 4612,1840.44 ; 5317.03,2859.97 U16.2@5579.94,2859.97 U16.4@5819.94,2859.97 5879.91,2800 C88.1@6010,2800 ; 5317.03,2859.97 R7.1@5297,2880 5317.03,2859.97
  Bottom Layer w10: JTAG.1@244,1934 JTAG.2@144,1934 144,1590 501,1233 501,875 584,792 640,792 712,864 v1(712,1118) ; OV2640.1@340,60 383,17 1500.81,17 1645,161.19 1763.81,161.19 1885.53,39.47 2559.47,39.47 U13.3@2620,100 ; v1(390,3740) 524.61,3605.39 554.61,3605.39 ; v1(562,3803) 357,3803 ; v1(1379.38,3845.38) 1202.38,3845.38 1157,3800 1157,3640 1191.61,3605.39 ; v1(1401.56,3826.44) 1986.56,3826.44 v1(2034,3779) ; v1(1877,2630) v1(1927.22,2579.78) ; v1(2137,4296) 2145.5,4287.5 2472.88,4287.5 2486.5,4273.88 2889.88,4273.88 2963,4347 2963,4356 ; BEEP.1@2180,180 2920,180 ; v1(2634,194) 2634,192 2920,180 ; v1(2801,2741) 2801,2725 v1(2734,2658) v1(2902,2658) ; v1(2845,3178) v1(2952.5,3178) ; TFTLCD.24@3099.92,4500.24 3163.16,4437 ; TFTLCD.25@3199.92,4400.24 3163.16,4437 ; v1(3489,161) 3449.41,121.41 2978.59,121.41 U12.1@2940,160 2920,180 ; v1(3546.56,161) v1(3675,161) ; v1(3819,527) 4227,527 BOOT.2@4340,640 4876,640 KEY_UP.1@4953,563 KEY_UP.1@5208.91,563 ; v1(4120,3608.19) v1(4233,3721.19) ; v1(4142.5,3855.5) 4142.5,3910.5 3771,4282 3037,4282 2963,4356 ; v1(4340,1782) 4498,1782 v1(4584.22,1868.22) ; v1(4745,3202) v1(4600,3202) 4620,3222 5838,3222 ; v1(5381,3208) 5852,3208 ; v1(5479,3240) 5820,3240 5838,3222 ; VOUT1.2@6240,3020 VOUT1.4@6140,3020 VOUT1.6@6040,3020 5852,3208 ; 357,3803 U6.2@80,4080 357,3803 ; 357,3803 554.61,3605.39 ; 554.61,3605.39 1191.61,3605.39 ; 554.61,3605.39 1191.61,3605.39 ; 1191.61,3605.39 SD_CARD.4@1259.64,3605.39 ; 1191.61,3605.39 SD_CARD.4@1259.64,3605.39 ; 1191.61,3605.39 SD_CARD.4@1259.64,3605.39 ; 2963,4356 2963,4416 ; 2963,4356 2963,4416 ; 2963,4416 2984,4437 3163.16,4437 ; 5838,3222 5852,3208 ; 5838,3222 5852,3208
VCC3.3A: 94.2 C1.2 C2.2 C96.1 U2.31 U18.2 U18.4 | length 4313.2
  Top Layer w9.84: U2.31@5089.21,1257.59 5089.21,1227 5240.7,1227
  Top Layer w10: C2.2@5007.5,964.94 C1.2@5007.5,1024.94 5464.94,1024.94 5502,1062 ; 5240.7,1227 5303,1289.3 5303,1632 5314,1643 5464,1643 5502,1605 v1(5502,1558) ; U18.2@5579.94,2579.97 U18.4@5819.94,2579.97 ; v1(5663,1719) 5663,2080 5640,2103 5610,2103 5577,2136 5577,2392 5617,2432 5671.97,2432 U18.4@5819.94,2579.97 ; 94.2@5947.5,2439.94 C96.1@5947.5,2520 ; 5502,1062 v1(5502,1558) ; 5502,1062 v1(5502,1558) ; U18.4@5819.94,2579.97 5879.91,2520 C96.1@5947.5,2520 ; C96.1@5947.5,2520 C96.1@6010,2520 C96.1@5947.5,2520
  Bottom Layer w10: v1(5502,1558) v1(5663,1719)
VCC3.3E: C14.2 C15.2 C28.2 C29.2 EARTHNET.4 EARTHNET.5 L1.1 R3.2 R4.2 R5.2 R6.2 U1.1 U1.19 | length 3706.6
  Top Layer w9.84: 4431,3573 4494.79,3509.21 U1.1@4517.28,3509.21 4517.28,3738.28 ; 4649.21,3688 4649.21,3608 ; 4649.21,3608 U1.19@4649.21,3542.72 4649.21,3608
  Top Layer w10: L1.1@4142,3431 4142,3468 4142.5,3468.5 C28.2@4142.5,3507.19 ; C14.2@4142.5,3735.56 C15.2@4142.5,3659.44 4171,3630.94 4171,3535.69 C28.2@4142.5,3507.19 ; 4431,3573 4409,3573 4216,3380 4094,3380 4071,3403 4059.5,3403 4059.5,3459 4071,3459 4073,3461 4104,3461 4120,3477 4120,3507.19 C28.2@4142.5,3507.19 ; 4517.28,3738.28 4521,3742 4521,3874 v1(4564.5,3917.5) ; 4649.21,3608 v1(4737.21,3696) ; 4649.21,3688 4657.21,3696 v1(4662,3696) ; R6.2@5002.5,3265.94 R5.2@5002.5,3305.94 R4.2@5002.5,3345.94 R3.2@5002.5,3385.94 5164.87,3395.81 v1(5164.87,3696) ; EARTHNET.5@5235.2,4050 5235.2,4000 EARTHNET.4@5285.2,3950 ; v1(5164.87,3696) C29.2@5164.87,3757.5 v1(5164.87,3696)
  Bottom Layer w10: v1(4564.5,3917.5) 4568,3917.5 4600,3885.5 4600,3712 4616,3696 v1(4662,3696) ; v1(4737.21,3696) v1(5164.87,3696) 5285.2,3816.32 EARTHNET.4@5285.2,3950
VCC5: C38.1 C69.2 C75.1 C87.1 C91.2 C92.2 C95.2 C97.2 D5.2 K1.2 MOS1.2 R1.2 R56.2 TFTLCD.28 U7.6 U10.3 U16.3 U17.16 U18.3 VOUT2.2 VOUT2.4 VOUT2.6 | length 18703.7
  Top Layer w10: C97.2@440.06,887.5 C91.2@480.06,887.5 C92.2@520.06,887.5 526,893.44 v1(526,953) ; v1(567,1274) 585,1274 ; U17.16@585,942.36 585,1274 ; R56.2@859.94,1572.5 859.94,1541.66 862.6,1539 MOS1.2@862.6,1509.21 ; v1(1180,4703) 1054,4577 1054,4261 758,3965 608,3965 599.5,3956.5 599.5,3701.91 613.5,3687.91 613.5,3544 581.5,3512 552,3512 520,3480 U10.3@520,3400 520,3363 527,3356 C75.1@527,3320 866.68,2980.32 866.68,1768 886.68,1748 1016,1748 1059,1705 1059,1494 1016,1451 888,1451 862.6,1476.4 ; v1(3077,4703) 3077,4637 3159,4555 3245.16,4555 TFTLCD.28@3299.92,4500.24 3253,4453.31 3253,4280 C38.1@3273,4260 ; R1.2@4807.5,1024.94 4878.06,1024.94 v1(4903,1000) ; C95.2@5372.47,2479.97 5485.03,2479.97 ; U18.3@5579.94,2479.97 5485.03,2479.97 ; U16.3@5579.94,2759.97 5527.97,2759.97 5491,2723 5491,2623.56 ; C87.1@5587,3040 5641,3040 5646,3045 D5.2@5700,3045 5774,3056 5774,3112 5790,3128 5948,3128 VOUT2.6@6040,3220 ; K1.2@6120,3900 6163,3857 6163,3566 6097,3500 6097,3263 VOUT2.4@6140,3220 6097,3177 6097,2906 6104,2899 6104,2636 ; U7.6@6240.43,1819.58 6192.86,1819.58 C69.2@6159.94,1852.5 6104,1908.44 6104,2636 ; 585,1274 768.6,1274 ; 585,1274 768.6,1274 ; 768.6,1274 862.6,1368 862.6,1476.4 ; 862.6,1476.4 MOS1.2@862.6,1509.21 ; 862.6,1476.4 MOS1.2@862.6,1509.21 ; 5485.03,2479.97 5485.03,2540.03 5491,2546 5491,2623.56 ; 5491,2623.56 5501.44,2634 5691,2634 5701,2644 6096,2644 6104,2636
  Bottom Layer w10: v1(526,953) 552,979 560,1274 v1(567,1274) ; v1(1180,4703) v1(3077,4703) ; TFTLCD.28@3299.92,4500.24 3337.16,4463 3915,4463 3970,4408 3970,4280 4023,4227 4448,4227 4470,4249 4470,4319 4547,4396 4547,4513 4600,4566 5574,4566 5738,4402 6104,4402 6152,4354 6152,3932 K1.2@6120,3900 ; v1(4903,1000) 4930,1000 5055,875 6220,875 6283,938 6283,1777 U7.6@6240.43,1819.58 ; VOUT2.6@6040,3220 VOUT2.4@6140,3220 VOUT2.2@6240,3220
VDDA: C46.2 C47.2 P7.2 R25.1 U4.33 | length 9291.6
  Top Layer w10: U4.33@3000.35,2769.9 3046.1,2769.9 3048,2768 3083,2768 3091,2776 3091,2802.5 3007,2886.5 R25.1@3007,3060 3059,3060 3059.06,3060.06 C47.2@3112.5,3060.06 C46.2@3112.5,3140.06 3092.94,3140.06 v1(3080,3153) ; v1(3155,3198) v1(3155,4057) ; v1(3364,4126) 3364,4336 3345,4355 3345,4540 3384,4579 3417,4579 3470,4632 3470,4682 3496,4708 v1(5469,4708) ; P7.2@4740,2200 4783,2157 v1(4783,2105) ; v1(4920,2105) v1(5014,2011) ; v1(6048,1981) v1(6048,2157) ; v1(6238,2942) v1(6283,2987)
  Bottom Layer w10: v1(3080,3153) 3110,3153 v1(3155,3198) ; v1(3155,4057) 3295,4057 v1(3364,4126) ; v1(4783,2105) v1(4920,2105) ; v1(5014,2011) 5221,2011 5268,1964 5690,1964 5707,1981 v1(6048,1981) ; v1(5469,4708) 5748,4429 6115,4429 6283,4261 v1(6283,2987) ; v1(6048,2157) 6048,2187.52 6140,2279.52 6140,2844 v1(6238,2942)
VREF+: C62.2 P7.1 U4.32 | length 2192.7
  Top Layer w10: v1(2951,2756) 2956.79,2750.21 U4.32@3000.35,2750.21 ; v1(3782,2644) 3788,2650 C62.2@3880.06,2650 3920.5,2650 3957.5,2613 3957.5,2528.5 3936,2507 v1(3936,2419)
  Bottom Layer w10: v1(2951,2756) 2968,2739 3387,2739 3404,2756 3536,2756 3644,2648 3778,2648 v1(3782,2644) ; v1(3936,2419) 3999,2356 4684,2356 P7.1@4740,2300
VUSB: F1.2 USB_232.1 USB_SLAVE.1 | length 9315.3
  Top Layer w10: v1(285,562.99) USB_232.1@349.06,562.99 391.99,562.99 v1(473.09,644.09) ; v1(285,1062.99) USB_SLAVE.1@349.06,1062.99 ; v1(3336,1118) 3356,1138 3356,2011.05 3350.05,2017 3350.05,2090.05 3356,2096 3356,2225.45 3328.5,2252.95 3328.5,2814.45 3514,2999.95 v1(3514,3230) ; v1(6130,4104.46) F1.2@6130,4380.06
  Bottom Layer w10: v1(285,562.99) v1(285,1062.99) ; v1(473.09,644.09) 1384.09,644.09 1461.15,721.15 2939.15,721.15 v1(3336,1118) ; v1(3514,3230) 4002,3230 4035.5,3263.5 4350.08,3263.5 4353.83,3259.75 4806.75,3259.75 4824.5,3277.5 5303.04,3277.5 v1(6130,4104.46)
pads on no net: BAT.0 COM2.0 COM2.1 COM2.4 COM2.6 COM2.7 COM2.8 COM2.9 COM3.0 COM3.2 COM3.5 COM3.6 COM3.7 COM3.8 COM3.9 EARTHNET.7 JTAG.11 JTAG.17 JTAG.19 K1.1 K1.4 K1.5 K1.6 LINE_IN.0 PHONE.0 SD_CARD.10 SD_CARD.11 SD_CARD.12 TFTLCD. TFTLCD.32 U1.10 U2.15 U2.21 U2.22 U8.2 U8.3 U8.4 U8.5 U8.6 U8.7 U8.14 U8.15 U8.16 U8.17 U8.19 U8.21 U8.22 U10.5 U17.9 U17.10 U17.11 U17.12 U17.15 USB_232.4 USB_232.6 USB_232.7 USB_232.8 USB_232.9 USB_232.MH1 USB_232.MH2 USB_SLAVE.4 USB_SLAVE.6 USB_SLAVE.7 USB_SLAVE.8 USB_SLAVE.9 USB_SLAVE.MH1 USB_SLAVE.MH2 Y1. Y2. Y3. Y4.
copper on no net: | length 57.7
  Top Layer w10: 5885,482.27 5885,540
  other v3: 140,140 6160,140 6160,4580 140,4590

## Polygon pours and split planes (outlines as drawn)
GND on Top Layer "Top Layer-No Net" (solid, remove dead copper, pour order 1001): 6300,45 6300,4680 6255,4725 45,4725 0,4680 0,45 45,0 6255,0 6300,45
GND on Top Layer "Top Layer-No Net" (solid, remove dead copper, pour order 1000): 45,4725 0,4680 0,45 45,0 6255,0 6300,45 6300,4680 6255,4725 45,4725
GND on Bottom Layer "Top Layer-No Net" (solid, remove dead copper, pour order 1002): 6300,45 6300,4680 6255,4725 45,4725 0,4680 0,45 45,0 6255,0 6300,45

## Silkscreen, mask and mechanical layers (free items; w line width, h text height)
Top Overlay:
  rectangle: 5710,400 5950,450
  rectangle: 5680,330 5990,400
  rectangle: 5670,310 6000,330
  rectangle: 5730,450 5930,470
  lines w1: 5670,330 5680,400 5710,450 5730,470 ; 5690,170 5710,140 5760,70 5795.86,34.14 ccw(c5830,68.28) 5830,20 ; 5695.36,164.64 cw(c5780.71,250) 5660,250 5660,270 5660,350 cw(c5780.71,350) 5695.36,435.36 5740,480 cw(c5812.43,407.57) 5812.43,510 5840,510 5850,510 cw(c5850,389.29) 5935.36,474.64 5964.64,445.36 cw(c5879.29,360) 6000,360 6000,230 6000,224.14 cw(c5965.86,224.14) 5990,200 5930,100 5890,50 5850,20 5820,20 ; 5930,470 5950,450 5990,400 6000,330
  text "李振" at 645,3385 h280
  text "STM32F407" at 420,3130 h200
  text "学以致用" at 380,2915 h250
  text "厚积薄发" at 2525,715 h300
  text "志在必得" at 2550,440 h300
  text "TPAD" at 5730,390 h60
  text "TPAD" at 5720,230 h60
  text "PAD" at 5770,70 h50
Bottom Overlay:
  lines w10: 1545,1610 1830,1610 1835,1615 ; 1545,1900 1835,1900 ; 1545,2005 1835,2005 ; 1545,2315 1550,2320 1835,2320 ; 1550,1130 1835,1130 ; 1550,1225 1835,1225 ; 1550,1320 1835,1320 ; 1550,1415 1835,1415 ; 1550,1505 1830,1505 ; 1550,1705 1835,1705 ; 1550,1815 1835,1815 ; 1550,2100 1835,2100 ; 1550,2215 1835,2215 ; 1550,2405 1555,2410 1835,2410 ; 1550,2505 1835,2505 ; 1550,2610 1835,2610 ; 1550,2715 1840,2715 ; 1550,2810 1835,2810 ; 1550,2905 1835,2905 ; 1550,3015 1835,3015 ; 1550,3105 1835,3105 ; 1700,1015 1700,1225 ; 4290,1155 4545,1155 ; 4290,1355 4300,1355 4545,1355 ; 4290,1440 4305,1440 4545,1440 ; 4290,1765 4545,1765 ; 4290,1955 4545,1955 ; 4290,2050 4545,2050 ; 4290,2155 4545,2155 ; 4290,2260 4545,2260 ; 4290,2355 4545,2355 ; 4290,2455 4545,2455 ; 4290,2555 4545,2555 ; 4290,2655 4545,2655 ; 4290,2750 4545,2750 ; 4290,2850 4545,2850 ; 4290,3055 4545,3055 ; 4290,3155 4545,3155 ; 4290,3250 4290,3270 4545,3270 4545,3255 4545,1080 4515,1050 4290,1050 4290,3255 ; 4295,1255 4305,1255 4545,1255 ; 4295,1545 4300,1545 4545,1545 ; 4295,1645 4300,1645 4545,1645 ; 4295,1860 4545,1860 ; 4295,2960 4545,2960 ; 4790,2250 5080,2250 ; 5080,1685 5565,1685 ; 5080,1800 5090,1800 5565,1800 ; 5080,1905 5565,1905 ; 5080,2010 5080,1580 5085,1575 5560,1575 5565,1570 5565,2005 ; 5080,2115 5570,2115 ; 5080,2150 4790,2150 4790,2350 5080,2350 ; 5080,2220 5085,2215 5570,2215 ; 5080,2300 5080,2410 5075,2415 5575,2415 5575,2400 5575,2315 ; 5325,2315 5330,2310 5330,2005 ; 5330,1575 5330,1905 ; 5570,2010 5570,2315 ; 5800,2005 5800,2310 ; 6025,1975 6030,1980 6190,1980 ; 6025,2070 6190,2070 ; 6025,2175 6190,2175 ; 6025,2270 6190,2270 ; 6190,1885 6190,1775 6035,1775 6025,1785 6025,1880 ; 6190,2370 6190,1880 6025,1880 ; 6190,2375 6025,2375 6025,1880 ; 1550,1015 1550,3210 1830,3210 1835,3205 1835,1015 1550,1015 ; 5080,2005 6005,2005 6025,2025 6025,2285 6000,2310 5085,2310 5080,2305 5080,2005
  text "B" at 5935,4660 h50
  text "A" at 5700,4655 h50
  text "H" at 340,4615 h60
  text "CAN" at 560,4615 h60
  text "L" at 645,4615 h60
  text "COM3" at 4435,4510 h80
  text "COM2" at 1520,4500 h80
  text "485" at 5885,4440 h60
  text "DC_IN" at 6235,4290 h60 r90
  text "5-12V" at 6140,4275 h50 r90
  text "GND" at 280,3985 h40
  text "3.3V" at 155,3980 h40
  text "24L01" at 260,3890 h50
  text "SWITCH" at 6250,3770 h50
  text "李振" at 3800,3625 h200
  text "GND" at 5980,3300 h50
  text "LZ--STM32F407" at 4080,3290 h200
  text "5V" at 5985,3190 h50
  text "B12" at 4400,3185 h40
  text "GND" at 4525,3185 h40
  text "GND" at 1680,3145 h40
  text "B14" at 1810,3145 h40
  text "GND" at 5980,3100 h50
  text "G1" at 4380,3085 h40
  text "B13" at 4525,3085 h40
  text "D11" at 1815,3040 h40
  text "B15" at 1685,3035 h40
  text "3.3V" at 5975,2990 h50
  text "F15" at 4405,2985 h40
  text "G0" at 4520,2985 h40
  text "D12" at 1685,2940 h40
  text "D13" at 1815,2940 h40
  text "F13" at 4400,2885 h40
  text "F14" at 4525,2885 h40
  text "GND" at 85,2855 h50 r90
  text "G3" at 1795,2840 h40
  text "G2" at 1675,2830 h40
  text "F11" at 4390,2780 h40
  text "F12" at 4525,2780 h40
  text "G5" at 1800,2745 h40
  text "G4" at 1670,2740 h40
  text "TX" at 610,2720 h40
  text "RX" at 925,2720 h40
  text "GND" at 85,2680 h50 r90
  text "B1" at 4370,2680 h40
  text "B2" at 4520,2680 h40
  text "G6" at 1670,2650 h40
  text "G7" at 1805,2640 h40
  text "A9" at 925,2625 h40
  text "RESET" at 465,2610 h40
  text "A10" at 605,2605 h40
  text "C5" at 4400,2585 h40
  text "B0" at 4520,2585 h40
  text "C6" at 1805,2545 h40
  text "G8" at 1675,2535 h40
  text "JTDO" at 450,2515 h45
  text "GND" at 80,2510 h50 r90
  text "C4" at 4520,2490 h40
  text "A7" at 4400,2485 h40
  text "JTMS" at 1000,2445 h40
  text "3.3V" at 610,2440 h40
  text "C8" at 1805,2435 h40
  text "C7" at 1665,2430 h40
  text "A5" at 4400,2380 h40
  text "A6" at 4515,2375 h40
  text "A8" at 1805,2355 h40
  text "GND" at 605,2350 h40
  text "JTCK" at 1005,2350 h40
  text "GND" at 80,2345 h50 r90
  text "C9" at 1670,2345 h40
  text "P10" at 5440,2330 h60
  text "JTCK" at 450,2315 h45
  text "LED" at 6170,2290 h50
  text "A0" at 4405,2285 h40
  text "A4" at 4515,2285 h40
  text "VREF+" at 5040,2275 h50
  text "JTMS" at 450,2245 h45
  text "A13" at 1685,2245 h40
  text "A14" at 1815,2245 h40
  text "U3-RX" at 5310,2245 h45
  text "U3-TX" at 5550,2245 h45
  text "KEY" at 6170,2200 h50
  text "CAN-TX" at 600,2185 h40
  text "C3" at 4400,2185 h40
  text "A1" at 4515,2185 h40
  text "GND" at 85,2175 h50 r90
  text "CAN-RX" at 1085,2175 h40
  text "VDDA" at 5040,2170 h50
  text "PB10" at 5295,2140 h45
  text "PB11" at 5540,2140 h45
  text "C10" at 1815,2135 h40
  text "A15" at 1680,2125 h40
  text "JTDI" at 435,2115 h45
  text "RX" at 6170,2095 h50
  text "A12" at 600,2090 h40
  text "C2" at 4525,2085 h40
  text "C1" at 4390,2075 h40
  text "A11" at 930,2070 h40
  text "G-RX" at 5305,2040 h45
  text "G-TX" at 5545,2040 h45
  text "C11" at 1675,2035 h40
  text "C12" at 1805,2035 h40
  text "3.3V" at 90,2020 h50 r90
  text "JTRST" at 480,2010 h45
  text "TX" at 6175,2000 h50
  text "DP" at 600,1985 h40
  text "DM" at 930,1980 h40
  text "F10" at 4420,1980 h40
  text "C0" at 4520,1980 h40
  text "D2" at 1660,1940 h40
  text "D3" at 1805,1935 h40
  text "3.3V" at 450,1920 h45
  text "P9" at 5395,1920 h60
  text "F9" at 4525,1895 h40
  text "GND" at 6170,1895 h50
  text "F8" at 4400,1890 h40
  text "D4" at 1665,1835 h40
  text "D5" at 1805,1830 h40
  text "485T" at 5305,1820 h50
  text "485R" at 5545,1815 h50
  text "5V" at 6165,1795 h50
  text "F6" at 4410,1790 h40
  text "F7" at 4525,1790 h40
  text "D6" at 1665,1730 h40
  text "D7" at 1810,1730 h40
  text "PA3" at 5285,1715 h50
  text "PA2" at 5520,1710 h50
  text "F4" at 4410,1680 h40
  text "F5" at 4525,1680 h40
  text "G10" at 1810,1635 h40
  text "G9" at 1655,1630 h40
  text "U2-R" at 5295,1600 h50
  text "U2-T" at 5540,1600 h50
  text "F2" at 4400,1575 h40
  text "F3" at 4525,1570 h40
  text "G11" at 1660,1540 h40
  text "G12" at 1815,1535 h40
  text "F0" at 4405,1470 h40
  text "F1" at 4520,1465 h40
  text "G13" at 1670,1435 h40
  text "G14" at 1810,1435 h40
  text "E6" at 4390,1375 h40
  text "C13" at 4530,1375 h40
  text "G15" at 1670,1350 h40
  text "B3" at 1800,1350 h40
  text "E4" at 4400,1280 h40
  text "E5" at 4520,1280 h40
  text "B4" at 1660,1255 h40
  text "B5" at 1800,1250 h40
  text "E2" at 4400,1180 h40
  text "E3" at 4515,1180 h40
  text "B6" at 1670,1160 h40
  text "B7" at 1800,1150 h40
  text "E1" at 4515,1085 h40
  text "E0" at 4405,1080 h40
  text "B8" at 1675,1055 h40
  text "B9" at 1800,1050 h40
  text "+" at 5490,805 h50
  text "GND" at 6175,780 h50
  text "3.3V" at 4595,725 h50
  text "GND" at 4070,720 h50
  text "DAC" at 5855,675 h50
  text "DAC" at 6055,675 h50
  text "KEY_UP" at 5185,655 h50
  text "GND" at 4070,620 h50
  text "3.3V" at 4600,605 h50
  text "PWM" at 5845,570 h50
  text "ADC" at 6060,570 h50
  text "T_PAD" at 6185,470 h50
  text "RESET" at 4390,390 h50
  text "K0" at 5450,320 h50
  text "K1" at 5105,310 h50
  text "K2" at 4765,305 h50
  text "GND" at 375,295 h40
  text "3.3V" at 2200,235 h40
  text "3.3V" at 385,220 h40
  text "3.3V" at 2995,195 h40
  text "GND" at 3175,195 h40
  text "GND" at 3305,195 h40
  text "T_PAD" at 5940,165 h50
  text "GND" at 1360,90 h40 r90
  text "1WIREQ" at 3150,55 h45
Mechanical 1:
  lines w7: -1.23,41.23 -1.23,4683.77 ; 40,0 6260,0 ; 41.23,4726.23 6258.77,4726.23 ; 6300,40 6300,4685
  lines w10: -1.23,41.23 ccw(c40,41.23) 40,0 ; -1.23,4683.77 cw(c40,4683.77) 40,4725 ; 6258.77,-1.23 ccw(c6258.77,40) 6300,40 ; 6258.77,4726.23 cw(c6258.77,4685) 6300,4685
